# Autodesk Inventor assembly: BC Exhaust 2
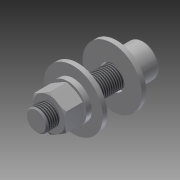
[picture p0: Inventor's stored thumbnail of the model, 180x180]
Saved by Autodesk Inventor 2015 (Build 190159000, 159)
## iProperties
Created: 2007-02
Part Number: BC Exhaust 2
Document SubType Name: Assembly
Designer: Autodesk, Inc.
Mass: 139.846 g
Surface Area: 109.169 cm^2
Volume: 17.7921 cm^3
Density: 7.86 g/cm^3
ClientObjectVersion: 1
Author: Autodesk, Inc.
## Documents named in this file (5)
- C:\Users\Public\Documents\Autodesk\Inventor 2015\Samples\Models\Assemblies\Blower\Blower\Design Accelerator\BC Exhaust 11.iam
- C:\Users\Public\Documents\Autodesk\Inventor 2015\Samples\Standard Parts\en-US\ANSI B18.22.1\ANSI B18.22.1 - 1_2 - wide - Type A.ipt
- C:\Users\Public\Documents\Autodesk\Inventor 2015\Samples\Standard Parts\en-US\ANSI B18.21.1\ANSI B18.21.1 - 0.5.ipt
- C:\Users\Public\Documents\Autodesk\Inventor 2015\Samples\Standard Parts\en-US\ANSI B18.3(13)\ANSI B18.3 - 1_2-20 UNF - 2(22).ipt
- C:\Users\Public\Documents\Autodesk\Inventor 2015\Samples\Standard Parts\en-US\ANSI B18.2.2(09)\ANSI B18.2.2 - 1_2 - 20(2).ipt
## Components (6 placed, 4 different names)
1. ANSI B18.22.1 - 1/2 - wide - Type A:1
2. ANSI B18.21.1 - 0.5:2
3. ANSI B18.3 - 1/2-20 UNF - 2:3
4. ANSI B18.22.1 - 1/2 - wide - Type A:4
5. ANSI B18.21.1 - 0.5:5
6. ANSI B18.2.2 - 1/2 - 20:6
